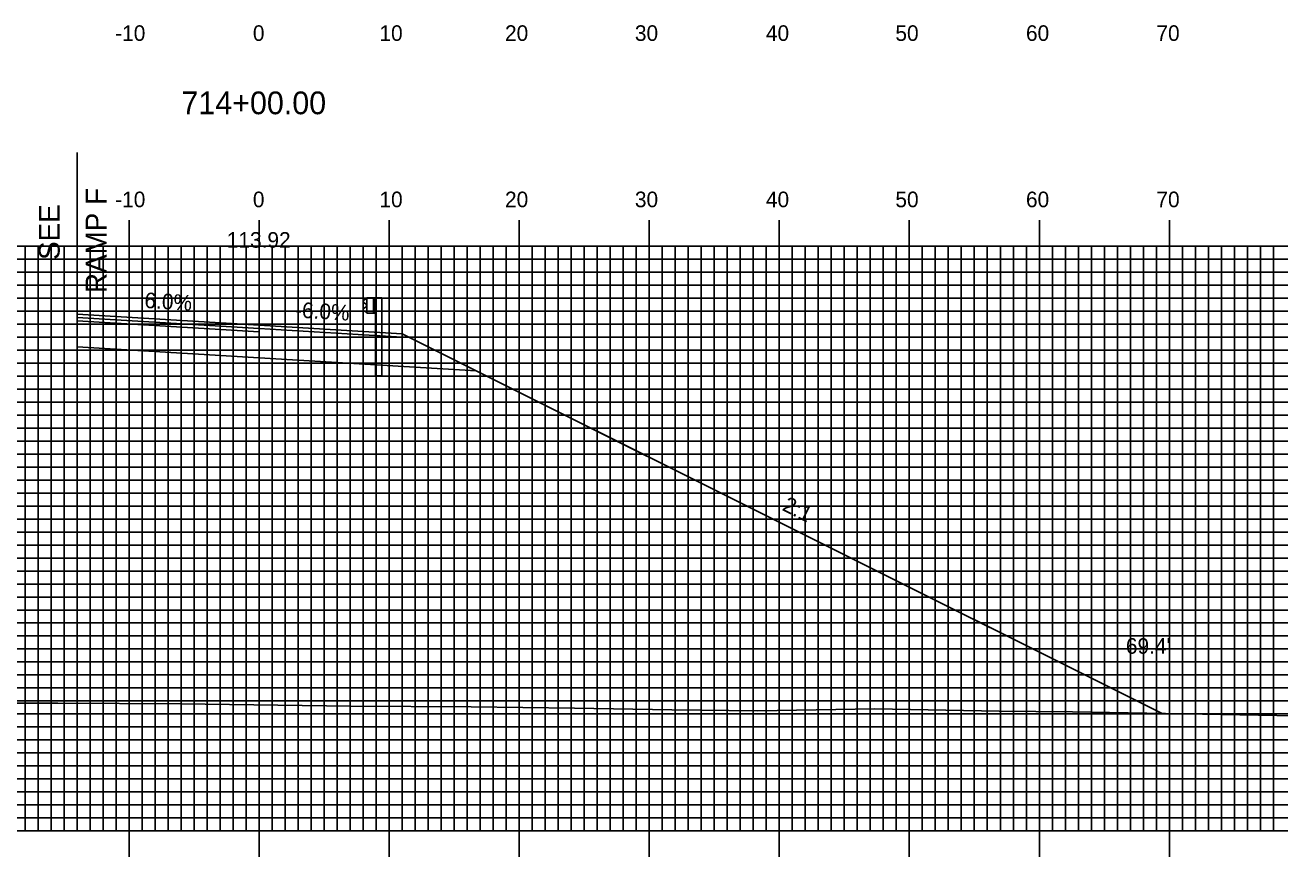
# Model space of a CAD drawing. Extents: x 855690 to 856034, y 364366 to 364586.
# Drawn here: x 855838.3 to 855934.8, y 364446.8 to 364510.8 of the extents above; entities that cross this region are included whole.
import ezdxf

# ---------------------------------------------------------------- set-up
doc = ezdxf.new("R2010")
doc.units = 0
for name, color, linetype in [('ANNOTATION', 7, 'Continuous'), ('D_Guardrail_Beam_Rt', 7, 'Continuous'), ('D_Roadway_Centerline', 7, 'Continuous'), ('D_Roadway_Centerline_Text', 7, 'Continuous'), ('D_Roadway_Edge_Shoulder', 7, 'Continuous'), ('D_Roadway_Edge_TW', 7, 'Continuous'), ('D_Roadway_Pavement', 7, 'Continuous'), ('D_Roadway_SlopeLines', 7, 'Continuous'), ('D_Roadway_SubGrade', 7, 'Continuous'), ('D_Text_Standard', 7, 'Continuous'), ('H_V ANNOTATION', 7, 'Continuous'), ('MAJOR', 7, 'Continuous'), ('MINOR', 7, 'Continuous'), ('S_Roadway_Centerline', 7, 'Continuous')]:
    doc.layers.add(name, color=color, linetype=linetype)

msp = doc.modelspace()

# ---------------------------------------------------------------- linework, layer by layer
at = {"layer": 'D_Guardrail_Beam_Rt'}
for p, q in [((855864.464, 364489.703), (855864.32, 364489.603)), ((855864.32, 364489.459), (855864.516, 364489.323)), ((855864.554, 364489.724), (855864.48, 364489.709)), ((855864.549, 364489.259), (855864.549, 364489.189)), ((855864.554, 364489.807), (855865.241, 364489.807)), ((855864.554, 364488.64), (855864.554, 364489.807)), ((855865.075, 364489.807), (855865.075, 364488.64)), ((855865.179, 364489.807), (855865.179, 364488.64)), ((855865.241, 364489.807), (855865.712, 364489.807)), ((855865.241, 364489.807), (855865.241, 364488.64)), ((855865.712, 364489.807), (855865.712, 364483.807)), ((855864.516, 364489.124), (855864.32, 364488.988)), ((855864.32, 364488.845), (855864.464, 364488.745)), ((855864.48, 364488.738), (855864.554, 364488.724)), ((855865.241, 364488.64), (855864.554, 364488.64)), ((855865.221, 364483.807), (855865.221, 364488.64)), ((855865.221, 364483.807), (855865.712, 364483.807))]:
    msp.add_line(p, q, dxfattribs=at)
for centre, major_axis, start_param, end_param in [((855864.371, 364489.531), (-0.0877, 0), 5.323254, 7.243116), ((855864.488, 364489.669), (-0.0417, 0), 4.907132, 5.323254), ((855864.471, 364489.259), (0.0789, 0), 0, 0.959931), ((855864.471, 364489.189), (0.0789, 0), 5.323254, 6.283185), ((855864.371, 364488.917), (-0.0877, 0), 5.323254, 7.243116), ((855864.488, 364488.779), (-0.0417, 0), 0.959931, 1.376053)]:
    msp.add_ellipse(centre, major_axis=major_axis, ratio=0.995501, start_param=start_param, end_param=end_param, dxfattribs=at)
at = {"layer": 'D_Roadway_Centerline'}
msp.add_lwpolyline([(855842.283, 364488.544), (855856.283, 364487.704), (855864.283, 364487.224), (855867.283, 364487.044), (855872.965, 364484.203), (855925.722, 364457.825)], dxfattribs=at)
at = {"layer": 'D_Roadway_Edge_Shoulder'}
msp.add_lwpolyline([(855856.283, 364487.704), (855864.283, 364487.224), (855864.283, 364487.224), (855867.283, 364487.044), (855867.283, 364486.794), (855856.283, 364487.454)], close=True, dxfattribs=at)
at = {"layer": 'D_Roadway_Edge_TW'}
msp.add_lwpolyline([(855842.283, 364488.544), (855856.283, 364487.704), (855856.283, 364487.454), (855842.283, 364488.294)], close=True, dxfattribs=at)
at = {"layer": 'D_Roadway_Pavement'}
msp.add_lwpolyline([(855842.283, 364488.294), (855856.283, 364487.454), (855856.283, 364487.204), (855842.283, 364488.044)], close=True, dxfattribs=at)
msp.add_lwpolyline([(855856.283, 364487.454), (855856.283, 364487.204)], dxfattribs=at)
msp.add_lwpolyline([(855856.283, 364487.454), (855856.283, 364487.204)], dxfattribs=at)
at = {"layer": 'D_Roadway_SlopeLines'}
msp.add_lwpolyline([(855867.283, 364487.044), (855925.722, 364457.825)], dxfattribs=at)
at = {"layer": 'D_Roadway_SubGrade'}
msp.add_line((855842.283, 364501.001), (855842.283, 364486.044), dxfattribs=at)
for points in [[(855842.283, 364488.044), (855856.283, 364487.204), (855856.283, 364485.204), (855842.283, 364486.044)], [(855856.283, 364487.204), (855856.283, 364487.454), (855867.283, 364486.794), (855867.283, 364487.044), (855872.965, 364484.203), (855856.283, 364485.204)]]:
    msp.add_lwpolyline(points, close=True, dxfattribs=at)
at = {"layer": 'MAJOR'}
for p, q in [((855846.283, 364495.791), (855846.283, 364493.787)), ((855856.283, 364495.791), (855856.283, 364493.787)), ((855866.283, 364495.791), (855866.283, 364493.787)), ((855876.283, 364495.791), (855876.283, 364493.787)), ((855886.283, 364495.791), (855886.283, 364493.787)), ((855896.283, 364495.791), (855896.283, 364493.787)), ((855906.283, 364495.791), (855906.283, 364493.787)), ((855916.283, 364495.791), (855916.283, 364493.787)), ((855926.283, 364495.791), (855926.283, 364493.787)), ((855716.283, 364493.787), (855996.283, 364493.787)), ((855716.283, 364493.787), (855996.283, 364493.787)), ((855846.283, 364448.787), (855846.283, 364493.787)), ((855856.283, 364448.787), (855856.283, 364493.787)), ((855866.283, 364448.787), (855866.283, 364493.787)), ((855876.283, 364448.787), (855876.283, 364493.787)), ((855886.283, 364448.787), (855886.283, 364493.787)), ((855896.283, 364448.787), (855896.283, 364493.787)), ((855906.283, 364448.787), (855906.283, 364493.787)), ((855916.283, 364448.787), (855916.283, 364493.787)), ((855926.283, 364448.787), (855926.283, 364493.787)), ((855716.283, 364488.787), (855996.283, 364488.787)), ((855716.283, 364483.787), (855996.283, 364483.787)), ((855716.283, 364478.787), (855996.283, 364478.787)), ((855716.283, 364473.787), (855996.283, 364473.787)), ((855716.283, 364468.787), (855996.283, 364468.787)), ((855716.283, 364463.787), (855996.283, 364463.787)), ((855716.283, 364458.787), (855996.283, 364458.787)), ((855716.283, 364453.787), (855996.283, 364453.787)), ((855716.283, 364448.787), (855996.283, 364448.787)), ((855716.283, 364448.787), (855996.283, 364448.787)), ((855846.283, 364446.783), (855846.283, 364448.787)), ((855856.283, 364446.783), (855856.283, 364448.787)), ((855866.283, 364446.783), (855866.283, 364448.787)), ((855876.283, 364446.783), (855876.283, 364448.787)), ((855886.283, 364446.783), (855886.283, 364448.787)), ((855896.283, 364446.783), (855896.283, 364448.787)), ((855906.283, 364446.783), (855906.283, 364448.787)), ((855916.283, 364446.783), (855916.283, 364448.787)), ((855926.283, 364446.783), (855926.283, 364448.787))]:
    msp.add_line(p, q, dxfattribs=at)
at = {"layer": 'MINOR'}
for p, q in [((855838.283, 364448.787), (855838.283, 364493.787)), ((855839.283, 364448.787), (855839.283, 364493.787)), ((855840.283, 364448.787), (855840.283, 364493.787)), ((855841.283, 364448.787), (855841.283, 364493.787)), ((855842.283, 364448.787), (855842.283, 364493.787)), ((855843.283, 364448.787), (855843.283, 364493.787)), ((855844.283, 364448.787), (855844.283, 364493.787)), ((855845.283, 364448.787), (855845.283, 364493.787)), ((855847.283, 364448.787), (855847.283, 364493.787)), ((855848.283, 364448.787), (855848.283, 364493.787)), ((855849.283, 364448.787), (855849.283, 364493.787)), ((855850.283, 364448.787), (855850.283, 364493.787)), ((855851.283, 364448.787), (855851.283, 364493.787)), ((855852.283, 364448.787), (855852.283, 364493.787)), ((855853.283, 364448.787), (855853.283, 364493.787)), ((855854.283, 364448.787), (855854.283, 364493.787)), ((855855.283, 364448.787), (855855.283, 364493.787)), ((855857.283, 364448.787), (855857.283, 364493.787)), ((855858.283, 364448.787), (855858.283, 364493.787)), ((855859.283, 364448.787), (855859.283, 364493.787)), ((855860.283, 364448.787), (855860.283, 364493.787)), ((855861.283, 364448.787), (855861.283, 364493.787)), ((855862.283, 364448.787), (855862.283, 364493.787)), ((855863.283, 364448.787), (855863.283, 364493.787)), ((855864.283, 364448.787), (855864.283, 364493.787)), ((855865.283, 364448.787), (855865.283, 364493.787)), ((855867.283, 364448.787), (855867.283, 364493.787)), ((855868.283, 364448.787), (855868.283, 364493.787)), ((855869.283, 364448.787), (855869.283, 364493.787)), ((855870.283, 364448.787), (855870.283, 364493.787)), ((855871.283, 364448.787), (855871.283, 364493.787)), ((855872.283, 364448.787), (855872.283, 364493.787)), ((855873.283, 364448.787), (855873.283, 364493.787)), ((855874.283, 364448.787), (855874.283, 364493.787)), ((855875.283, 364448.787), (855875.283, 364493.787)), ((855877.283, 364448.787), (855877.283, 364493.787)), ((855878.283, 364448.787), (855878.283, 364493.787)), ((855879.283, 364448.787), (855879.283, 364493.787)), ((855880.283, 364448.787), (855880.283, 364493.787)), ((855881.283, 364448.787), (855881.283, 364493.787)), ((855882.283, 364448.787), (855882.283, 364493.787)), ((855883.283, 364448.787), (855883.283, 364493.787)), ((855884.283, 364448.787), (855884.283, 364493.787)), ((855885.283, 364448.787), (855885.283, 364493.787)), ((855887.283, 364448.787), (855887.283, 364493.787)), ((855888.283, 364448.787), (855888.283, 364493.787)), ((855889.283, 364448.787), (855889.283, 364493.787)), ((855890.283, 364448.787), (855890.283, 364493.787)), ((855891.283, 364448.787), (855891.283, 364493.787)), ((855892.283, 364448.787), (855892.283, 364493.787)), ((855893.283, 364448.787), (855893.283, 364493.787)), ((855894.283, 364448.787), (855894.283, 364493.787)), ((855895.283, 364448.787), (855895.283, 364493.787)), ((855897.283, 364448.787), (855897.283, 364493.787)), ((855898.283, 364448.787), (855898.283, 364493.787)), ((855899.283, 364448.787), (855899.283, 364493.787)), ((855900.283, 364448.787), (855900.283, 364493.787)), ((855901.283, 364448.787), (855901.283, 364493.787)), ((855902.283, 364448.787), (855902.283, 364493.787)), ((855903.283, 364448.787), (855903.283, 364493.787)), ((855904.283, 364448.787), (855904.283, 364493.787)), ((855905.283, 364448.787), (855905.283, 364493.787)), ((855907.283, 364448.787), (855907.283, 364493.787)), ((855908.283, 364448.787), (855908.283, 364493.787)), ((855909.283, 364448.787), (855909.283, 364493.787)), ((855910.283, 364448.787), (855910.283, 364493.787)), ((855911.283, 364448.787), (855911.283, 364493.787)), ((855912.283, 364448.787), (855912.283, 364493.787)), ((855913.283, 364448.787), (855913.283, 364493.787)), ((855914.283, 364448.787), (855914.283, 364493.787)), ((855915.283, 364448.787), (855915.283, 364493.787)), ((855917.283, 364448.787), (855917.283, 364493.787)), ((855918.283, 364448.787), (855918.283, 364493.787)), ((855919.283, 364448.787), (855919.283, 364493.787)), ((855920.283, 364448.787), (855920.283, 364493.787)), ((855921.283, 364448.787), (855921.283, 364493.787)), ((855922.283, 364448.787), (855922.283, 364493.787)), ((855923.283, 364448.787), (855923.283, 364493.787)), ((855924.283, 364448.787), (855924.283, 364493.787)), ((855925.283, 364448.787), (855925.283, 364493.787)), ((855927.283, 364448.787), (855927.283, 364493.787)), ((855928.283, 364448.787), (855928.283, 364493.787)), ((855929.283, 364448.787), (855929.283, 364493.787)), ((855930.283, 364448.787), (855930.283, 364493.787)), ((855931.283, 364448.787), (855931.283, 364493.787)), ((855932.283, 364448.787), (855932.283, 364493.787)), ((855933.283, 364448.787), (855933.283, 364493.787)), ((855934.283, 364448.787), (855934.283, 364493.787)), ((855716.283, 364492.787), (855996.283, 364492.787)), ((855716.283, 364491.787), (855996.283, 364491.787)), ((855716.283, 364490.787), (855996.283, 364490.787)), ((855716.283, 364489.787), (855996.283, 364489.787)), ((855716.283, 364487.787), (855996.283, 364487.787)), ((855716.283, 364486.787), (855996.283, 364486.787)), ((855716.283, 364485.787), (855996.283, 364485.787)), ((855716.283, 364484.787), (855996.283, 364484.787)), ((855716.283, 364482.787), (855996.283, 364482.787)), ((855716.283, 364481.787), (855996.283, 364481.787)), ((855716.283, 364480.787), (855996.283, 364480.787)), ((855716.283, 364479.787), (855996.283, 364479.787)), ((855716.283, 364477.787), (855996.283, 364477.787)), ((855716.283, 364476.787), (855996.283, 364476.787)), ((855716.283, 364475.787), (855996.283, 364475.787)), ((855716.283, 364474.787), (855996.283, 364474.787)), ((855716.283, 364472.787), (855996.283, 364472.787)), ((855716.283, 364471.787), (855996.283, 364471.787)), ((855716.283, 364470.787), (855996.283, 364470.787)), ((855716.283, 364469.787), (855996.283, 364469.787)), ((855716.283, 364467.787), (855996.283, 364467.787)), ((855716.283, 364466.787), (855996.283, 364466.787)), ((855716.283, 364465.787), (855996.283, 364465.787)), ((855716.283, 364464.787), (855996.283, 364464.787)), ((855716.283, 364462.787), (855996.283, 364462.787)), ((855716.283, 364461.787), (855996.283, 364461.787)), ((855716.283, 364460.787), (855996.283, 364460.787)), ((855716.283, 364459.787), (855996.283, 364459.787)), ((855716.283, 364457.787), (855996.283, 364457.787)), ((855716.283, 364456.787), (855996.283, 364456.787)), ((855716.283, 364455.787), (855996.283, 364455.787)), ((855716.283, 364454.787), (855996.283, 364454.787)), ((855716.283, 364452.787), (855996.283, 364452.787)), ((855716.283, 364451.787), (855996.283, 364451.787)), ((855716.283, 364450.787), (855996.283, 364450.787)), ((855716.283, 364449.787), (855996.283, 364449.787))]:
    msp.add_line(p, q, dxfattribs=at)
at = {"layer": 'S_Roadway_Centerline'}
msp.add_lwpolyline([(855834.033, 364458.608), (855840.798, 364458.607), (855850.268, 364458.569), (855863.321, 364458.379), (855872.575, 364458.342), (855880.537, 364458.239), (855888.029, 364458.106), (855894.596, 364458.015), (855903.625, 364458.176), (855913.198, 364457.992), (855918.832, 364457.946), (855935.98, 364457.644), (855940.152, 364457.597), (855950.471, 364457.571), (855959.462, 364457.606), (855962.972, 364457.563), (855982.862, 364456.94), (855984.281, 364456.897), (855984.407, 364456.892), (855984.547, 364456.894), (855996.283, 364456.908)], dxfattribs=at)

# ---------------------------------------------------------------- texts
at = {"layer": 'ANNOTATION'}
for s, height, rotation, p in [('RAMP F', 1.6, 90, (855844.544, 364490.181)), ('SEE', 1.6, 90, (855840.944, 364492.73)), ('6.0%', 1.2, 356.56637, (855847.437, 364489.038)), ('-6.0%', 1.2, 356.56637, (855859.015, 364488.307)), ('2:1', 1.2, 333.43495, (855896.436, 364473.503))]:
    msp.add_text(s, height=height, rotation=rotation, dxfattribs=at).set_placement(p)
at = {"layer": 'D_Roadway_Centerline_Text'}
msp.add_text('113.92', height=1.2, dxfattribs=at).set_placement((855853.795, 364493.671))
at = {"layer": 'D_Text_Standard'}
msp.add_text("69.4'", height=1.2, dxfattribs=at).set_placement((855922.939, 364462.42))
at = {"layer": 'H_V ANNOTATION'}
for s, height, p in [('-10', 1.2, (855845.213, 364509.587)), ('0', 1.2, (855855.801, 364509.587)), ('10', 1.2, (855865.534, 364509.587)), ('20', 1.2, (855875.191, 364509.587)), ('30', 1.2, (855885.18, 364509.587)), ('40', 1.2, (855895.255, 364509.587)), ('50', 1.2, (855905.212, 364509.587)), ('60', 1.2, (855915.255, 364509.587)), ('70', 1.2, (855925.287, 364509.587)), ('714+00.00', 1.75, (855850.306, 364503.943)), ('-10', 1.2, (855845.213, 364496.787)), ('0', 1.2, (855855.801, 364496.787)), ('10', 1.2, (855865.534, 364496.787)), ('20', 1.2, (855875.191, 364496.787)), ('30', 1.2, (855885.18, 364496.787)), ('40', 1.2, (855895.255, 364496.787)), ('50', 1.2, (855905.212, 364496.787)), ('60', 1.2, (855915.255, 364496.787)), ('70', 1.2, (855925.287, 364496.787))]:
    msp.add_text(s, height=height, dxfattribs=at).set_placement(p)

doc.saveas('drawing.dxf')
